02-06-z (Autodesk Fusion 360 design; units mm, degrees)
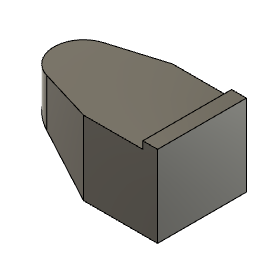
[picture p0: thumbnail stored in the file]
sketch "スケッチ1" plane through (0, 0, 0) normal (0, 0, 1) x axis (1, 0, 0)
  line L1 (-50, 25) -> (50, 25)
  line L2 (-50, -25) -> (-50, 25)
  line L3 (50, -25) -> (-50, -25)
  line L4 (50, 25) -> (50, -25)
  line L5 (-50, -25) -> (50, 25)
  line L6 (50, -25) -> (-50, 25)
  point P6 (0, 0)
  point P1 (0, 0)
  point P2 (50, 25)
  point P3 (-50, 25)
  point P5 (50, -25)
  horizontal L1
  perpendicular L1 L2
  parallel L1 L3
  parallel L2 L4
  coincident L5 P6
  coincident L6 P6
  coincident P1 P6
  dimension "d1" distance P2 P3 = 100
  dimension "d2" distance P2 P5 = 50
extrude "押し出し1" new body sketch "スケッチ1" profile of L1 L2 L3 L4 distance 60
sketch "スケッチ2" plane through (0, 25, 0) normal (0, 1, 0) x axis (-1, 0, 0)
  line L1 (50, 30) -> (50, -30)
  line L2 (-50, 30) -> (50, 30)
  line L3 (-50, -30) -> (-50, 30)
  line L4 (50, -30) -> (-50, -30)
  line L5 (-50, -30) -> (-40, -30)
  line L6 (-50, 30) -> (-50, -30)
  line L7 (-40, 30) -> (-50, 30)
  line L8 (-40, -30) -> (-40, 30)
  point P5 (-50, -30)
  point P7 (-50, -30)
  point P4 (-50, 30)
  point P8 (-50, 30)
  point P6 (-40, -30)
  horizontal L5
  vertical L6
  horizontal L7
  vertical L8
  coincident P5 P7
  coincident P4 P8
  dimension "d5" distance P6 P7 = 10
extrude "押し出し2" add sketch "スケッチ2" profile of L2 L3 L4 L5 L6 L7 L8 along normal blind 5
sketch "スケッチ4" plane through (0, 0, 30) normal (0, 0, 1) x axis (1, 0, 0)
  line L1 (50, 30) -> (50, -25)
  line L2 (40, 30) -> (50, 30)
  line L3 (40, 25) -> (40, 30)
  line L4 (-50, 25) -> (40, 25)
  line L5 (-50, -25) -> (-50, 25)
  line L6 (50, -25) -> (-50, -25)
  line L7 (0, -25) -> (-50, -25)
  line L8 (-50, 0) -> (0, -25)
  line L9 (-50, -25) -> (-50, 0)
  point P8 (-50, -25)
  point P10 (-50, 0)
  point P9 (0, -25)
  parallel L5 L9
  collinear L5 L9
  collinear L6 L7
  dimension "d10" distance P8 P10 = 25
  dimension "d11" distance P8 P9 = 50
extrude "押し出し3" cut sketch "スケッチ4" profile of L5 L6 L7 L8 L9 no distance stored
sketch "スケッチ5" plane through (0, 25, 0) normal (0, 1, 0) x axis (-1, 0, 0)
  line L1 (-40, -30) -> (-40, 30)
  line L2 (50, -30) -> (-40, -30)
  line L3 (50, 30) -> (50, -30)
  line L4 (-40, 30) -> (50, 30)
  line L5 (0, -30) -> (35.8055, -19.1389)
  line L6 (-50, -30) -> (0, -30)
  line L7 (-50, 30) -> (-50, -30)
  line L8 (0, 30) -> (-50, 30)
  line L9 (35.8055, 19.1389) -> (0, 30)
  line L10 (-50, -30) -> (-50, 30)
  arc A1 centre (30, 0) radius 20 clockwise from (35.8055, 19.1389) to (35.8055, -19.1389)
  point P7 (0, -30)
  point P8 (-50, -30)
  horizontal L6
  perpendicular L6 L7
  perpendicular L7 L8
  tangent L5 A1
  tangent L9 A1
  equal L5 L9
  equal L6 L8
  collinear L2 L6
  collinear L4 L8
  collinear L7 L10
  tangent L3 A1
  dimension "d13" distance P7 P8 = 50
  dimension "d14" radius A1 = 20
extrude "押し出し4" sketch "スケッチ5" profile of L1 L2 L4 L5 L6 L7 L8 L9 A1 L10 no distance stored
